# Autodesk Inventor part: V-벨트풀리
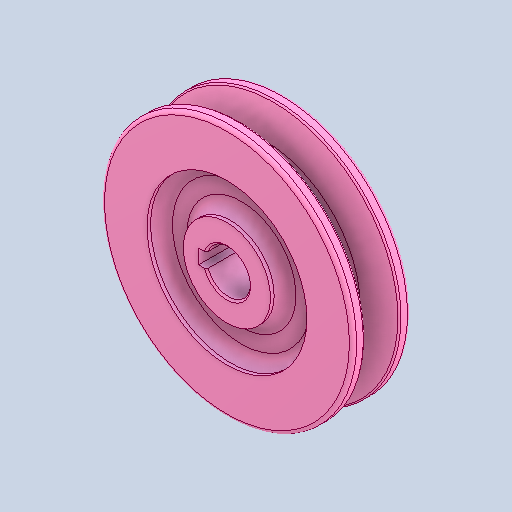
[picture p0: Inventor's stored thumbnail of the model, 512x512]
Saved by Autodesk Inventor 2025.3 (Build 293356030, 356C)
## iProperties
Created: 2025-08
Part Number: V-벨트풀리
Material: 강철, 연강
Document SubType Name: Modeling
Designer: infra011
Density: 7.86 g/cm^3
Appearance: 기본값
Author: jhkim
Sending System: Autodesk Inventor 2026
Preprocessor: ST-DEVELOPER v20.1
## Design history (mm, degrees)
feature "Solid1"
node "솔리드1"
